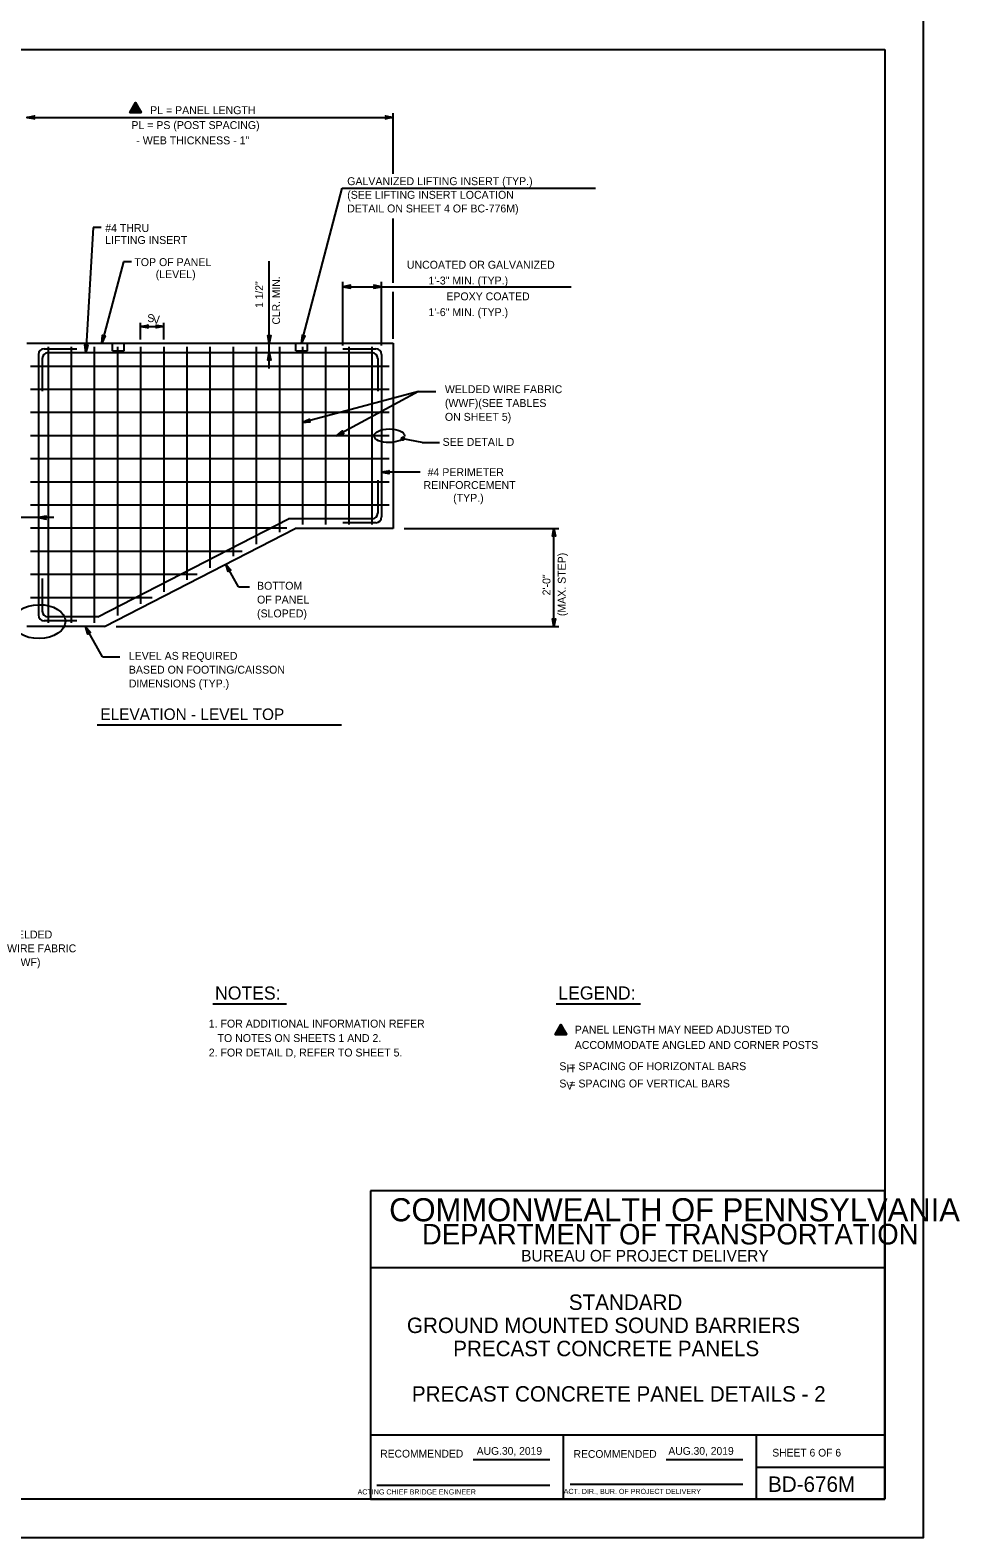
# Model space of a CAD drawing. Extents: x 3761 to 5458, y -616 to 1166.
# Drawn here: x 5096 to 5458, y -616 to -30 of the extents above; entities that cross this region are included whole.
import ezdxf

# ---------------------------------------------------------------- set-up
doc = ezdxf.new("R2010")
doc.units = 0
for name, color, linetype in [('1', 7, 'Continuous'), ('2', 7, 'Continuous'), ('PLT-BNDY', 7, 'Continuous')]:
    doc.layers.add(name, color=color, linetype=linetype)

msp = doc.modelspace()

# ---------------------------------------------------------------- linework, layer by layer
at = {"layer": '1'}
for p, q in [((5094.63, -63.74), (5237.13, -63.74)), ((5136.92, -60.5), (5136.92, -60.5)), ((5237.13, -85.73), (5237.13, -62.05)), ((5201.51, -151.51), (5217.37, -91.28)), ((5217.37, -91.28), (5315.89, -91.28)), ((5237.13, -128.07), (5237.13, -103.03)), ((5120.49, -106.64), (5117.63, -155.26)), ((5123.62, -106.64), (5120.49, -106.64)), ((5132.24, -119.99), (5123.81, -151.51)), ((5135.38, -119.99), (5132.24, -119.99)), ((5188.97, -161.48), (5188.97, -119.73)), ((5217.63, -152.49), (5217.63, -127.67)), ((5232.63, -152.49), (5232.63, -127.67)), ((5217.63, -129.63), (5306.42, -129.63)), ((5237.13, -149.92), (5237.13, -131.62)), ((5138.88, -150.2), (5138.88, -143.62)), ((5138.88, -145.08), (5147.88, -145.08)), ((5147.88, -150.2), (5147.88, -143.62)), ((5094.63, -151.51), (5237.13, -151.51)), ((5128.01, -154.51), (5128.01, -151.51)), ((5132.51, -154.51), (5132.51, -151.51)), ((5199.26, -154.51), (5199.26, -151.51)), ((5203.76, -154.51), (5203.76, -151.51)), ((5237.13, -151.51), (5237.13, -223.67)), ((5099.13, -156.01), (5099.13, -257.34)), ((5100.63, -157.51), (5100.63, -170.26)), ((5101.38, -153.76), (5114.13, -153.76)), ((5102.88, -153.01), (5102.88, -260.34)), ((5102.88, -155.26), (5228.88, -155.26)), ((5111.88, -153.01), (5111.88, -260.34)), ((5120.88, -153.01), (5120.88, -260.34)), ((5128.01, -154.51), (5132.51, -154.51)), ((5129.88, -153.01), (5129.88, -257.55)), ((5138.88, -153.01), (5138.88, -252.92)), ((5147.88, -153.01), (5147.88, -248.28)), ((5156.88, -153.01), (5156.88, -243.65)), ((5165.88, -153.01), (5165.88, -239.01)), ((5174.88, -153.01), (5174.88, -234.38)), ((5183.88, -153.01), (5183.88, -229.74)), ((5192.88, -153.01), (5192.88, -225.11)), ((5199.26, -154.51), (5203.76, -154.51)), ((5201.88, -153.01), (5201.88, -222.17)), ((5210.88, -153.01), (5210.88, -222.17)), ((5217.63, -153.76), (5230.38, -153.76)), ((5219.88, -153.01), (5219.88, -222.17)), ((5228.88, -153.01), (5228.88, -222.17)), ((5231.13, -157.51), (5231.13, -170.26)), ((5232.63, -156.01), (5232.63, -219.17)), ((5235.63, -160.59), (5096.13, -160.59)), ((5235.63, -169.59), (5096.13, -169.59)), ((5246.95, -170.37), (5201.88, -182.42)), ((5246.95, -170.37), (5215.05, -187.59)), ((5246.95, -170.37), (5253.68, -170.37)), ((5235.63, -178.59), (5096.13, -178.59)), ((5235.63, -187.59), (5096.13, -187.59)), ((5248.4, -190.25), (5240.91, -188.73)), ((5248.4, -190.25), (5255.14, -190.25)), ((5235.63, -196.59), (5096.13, -196.59)), ((5231.13, -204.92), (5231.13, -217.67)), ((5247.69, -201.75), (5232.63, -201.75)), ((5235.63, -205.59), (5096.13, -205.59)), ((5235.63, -214.59), (5096.13, -214.59)), ((5105.15, -219.44), (5057.23, -219.44)), ((5122.29, -258.09), (5196.41, -219.92)), ((5228.88, -219.92), (5196.41, -219.92)), ((5230.38, -221.42), (5217.63, -221.42)), ((5195.83, -223.59), (5096.13, -223.59)), ((5124.84, -261.84), (5198.96, -223.67)), ((5237.13, -223.67), (5198.96, -223.67)), ((5241.37, -223.67), (5301.6, -223.67)), ((5299.67, -261.84), (5299.67, -223.67)), ((5178.36, -232.59), (5096.13, -232.59)), ((5176.95, -246.34), (5172.01, -237.54)), ((5160.88, -241.59), (5096.13, -241.59)), ((5100.63, -243.09), (5100.63, -255.84)), ((5143.41, -250.59), (5096.13, -250.59)), ((5176.95, -246.34), (5181.32, -246.34)), ((5124.84, -261.84), (5094.63, -261.84)), ((5114.13, -259.59), (5101.38, -259.59)), ((5122.29, -258.09), (5102.88, -258.09)), ((5124.06, -273.62), (5117.45, -261.84)), ((5129.4, -261.84), (5301.6, -261.84)), ((5124.06, -273.62), (5130.8, -273.62)), ((5122.03, -300), (5217.08, -300)), ((5167.02, -408.54), (5195.59, -408.54)), ((5300.59, -408.54), (5333.38, -408.54)), ((5302.38, -419.19), (5302.38, -419.19))]:
    msp.add_line(p, q, dxfattribs=at)
for points in [[(5134.69, -61.79), (5139.15, -61.79), (5136.92, -57.92), (5134.69, -61.79)], [(5134.69, -61.79), (5136.92, -57.92), (5139.15, -61.79), (5134.69, -61.79), (5136.91, -58.03), (5139.08, -61.73), (5134.78, -61.74), (5136.92, -58.15), (5138.99, -61.68), (5134.88, -61.69), (5136.93, -58.26), (5138.89, -61.61), (5134.98, -61.64), (5136.92, -58.38), (5138.79, -61.56), (5135.09, -61.57), (5136.93, -58.51), (5138.68, -61.5), (5135.21, -61.5), (5136.92, -58.65), (5138.58, -61.44), (5135.31, -61.44), (5136.92, -58.79), (5138.47, -61.37), (5135.42, -61.38), (5136.92, -58.92), (5138.35, -61.3), (5135.52, -61.32), (5136.93, -59.04), (5138.21, -61.24), (5135.64, -61.25), (5136.93, -59.17), (5138.08, -61.15), (5135.76, -61.19), (5136.93, -59.32), (5137.96, -61.07), (5135.87, -61.13), (5136.93, -59.45), (5137.84, -61), (5136.01, -61.06), (5136.93, -59.58), (5137.73, -60.94), (5136.14, -61), (5136.93, -59.73), (5137.6, -60.87), (5136.28, -60.93), (5136.93, -59.86), (5137.47, -60.8), (5136.38, -60.86), (5136.92, -59.99), (5137.34, -60.73), (5136.51, -60.8), (5136.92, -60.11), (5137.24, -60.68), (5136.61, -60.74), (5136.92, -60.24), (5137.14, -60.62), (5136.72, -60.69), (5136.93, -60.36), (5137.05, -60.58), (5136.83, -60.61), (5136.92, -60.5), (5139.14, -61.77), (5136.92, -60.5), (5136.92, -57.95), (5136.93, -60.51), (5134.7, -61.78)], [(5094.63, -63.74), (5097.61, -63.18), (5097.38, -63.34), (5097.26, -63.54), (5097.23, -63.74), (5097.26, -63.94), (5097.38, -64.14), (5097.61, -64.3), (5094.63, -63.74), (5097.38, -64.14), (5097.26, -63.94), (5094.63, -63.74), (5097.23, -63.74), (5097.26, -63.54), (5094.63, -63.74), (5097.38, -63.34)], [(5237.13, -63.74), (5234.15, -64.3), (5234.38, -64.14), (5234.5, -63.94), (5234.53, -63.74), (5234.5, -63.54), (5234.38, -63.34), (5234.15, -63.18), (5237.13, -63.74), (5234.38, -63.34), (5234.5, -63.54), (5237.13, -63.74), (5234.53, -63.74), (5234.5, -63.94), (5237.13, -63.74), (5234.38, -64.14)], [(5217.63, -129.63), (5220.61, -130.18), (5220.5, -130.11), (5220.38, -130.03), (5220.33, -129.93), (5220.27, -129.83), (5220.25, -129.73), (5220.23, -129.63), (5220.25, -129.53), (5220.27, -129.43), (5220.33, -129.33), (5220.38, -129.23), (5220.5, -129.15), (5220.61, -129.07), (5217.63, -129.63), (5220.5, -129.15), (5220.38, -129.23), (5217.63, -129.63), (5220.33, -129.33), (5220.27, -129.43), (5217.63, -129.63), (5220.25, -129.53), (5220.23, -129.63), (5217.63, -129.63), (5220.25, -129.73), (5220.27, -129.83), (5217.63, -129.63), (5220.33, -129.93), (5220.38, -130.03), (5217.63, -129.63), (5220.5, -130.11)], [(5232.63, -129.63), (5229.65, -129.07), (5229.76, -129.15), (5229.88, -129.23), (5229.94, -129.33), (5230, -129.43), (5230.01, -129.53), (5230.03, -129.63), (5230.01, -129.73), (5230, -129.83), (5229.94, -129.93), (5229.88, -130.03), (5229.76, -130.11), (5229.65, -130.18), (5232.63, -129.63), (5229.76, -130.11), (5229.88, -130.03), (5232.63, -129.63), (5229.94, -129.93), (5230, -129.83), (5232.63, -129.63), (5230.01, -129.73), (5230.03, -129.63), (5232.63, -129.63), (5230.01, -129.53), (5230, -129.43), (5232.63, -129.63), (5229.94, -129.33), (5229.88, -129.23), (5232.63, -129.63), (5229.76, -129.15)], [(5138.88, -145.08), (5141.86, -144.52), (5141.63, -144.68), (5141.51, -144.88), (5141.48, -145.08), (5141.51, -145.28), (5141.63, -145.48), (5141.86, -145.64), (5138.88, -145.08), (5141.63, -145.48), (5141.51, -145.28), (5138.88, -145.08), (5141.48, -145.08), (5141.51, -144.88), (5138.88, -145.08), (5141.63, -144.68)], [(5147.88, -145.08), (5144.9, -145.64), (5145.13, -145.48), (5145.25, -145.28), (5145.28, -145.08), (5145.25, -144.88), (5145.13, -144.68), (5144.9, -144.52), (5147.88, -145.08), (5145.13, -144.68), (5145.25, -144.88), (5147.88, -145.08), (5145.28, -145.08), (5145.25, -145.28), (5147.88, -145.08), (5145.13, -145.48)], [(5117.63, -155.26), (5117.24, -152.25), (5117.39, -152.49), (5117.58, -152.62), (5117.78, -152.67), (5117.98, -152.64), (5118.19, -152.54), (5118.36, -152.32), (5117.63, -155.26), (5118.19, -152.54), (5117.98, -152.64), (5117.63, -155.26), (5117.78, -152.67), (5117.58, -152.62), (5117.63, -155.26), (5117.39, -152.49)], [(5123.81, -151.51), (5124.04, -148.49), (5124.09, -148.62), (5124.14, -148.75), (5124.22, -148.83), (5124.3, -148.92), (5124.39, -148.96), (5124.48, -149), (5124.58, -149.01), (5124.68, -149.02), (5124.8, -148.99), (5124.91, -148.96), (5125.01, -148.87), (5125.12, -148.77), (5123.81, -151.51), (5125.01, -148.87), (5124.91, -148.96), (5123.81, -151.51), (5124.8, -148.99), (5124.68, -149.02), (5123.81, -151.51), (5124.58, -149.01), (5124.48, -149), (5123.81, -151.51), (5124.39, -148.96), (5124.3, -148.92), (5123.81, -151.51), (5124.22, -148.83), (5124.14, -148.75), (5123.81, -151.51), (5124.09, -148.62)], [(5188.97, -151.51), (5188.41, -148.53), (5188.57, -148.76), (5188.77, -148.88), (5188.97, -148.91), (5189.17, -148.88), (5189.37, -148.76), (5189.53, -148.53), (5188.97, -151.51), (5189.37, -148.76), (5189.17, -148.88), (5188.97, -151.51), (5188.97, -148.91), (5188.77, -148.88), (5188.97, -151.51), (5188.57, -148.76)], [(5201.51, -151.51), (5202.87, -148.8), (5202.77, -148.89), (5202.66, -148.98), (5202.54, -149.01), (5202.43, -149.04), (5202.33, -149.03), (5202.23, -149.01), (5202.14, -148.97), (5202.05, -148.93), (5201.97, -148.84), (5201.89, -148.76), (5201.84, -148.62), (5201.8, -148.49), (5201.51, -151.51), (5201.84, -148.62), (5201.89, -148.76), (5201.51, -151.51), (5201.97, -148.84), (5202.05, -148.93), (5201.51, -151.51), (5202.14, -148.97), (5202.23, -149.01), (5201.51, -151.51), (5202.33, -149.03), (5202.43, -149.04), (5201.51, -151.51), (5202.54, -149.01), (5202.66, -148.98), (5201.51, -151.51), (5202.77, -148.89)], [(5188.97, -155.26), (5189.53, -158.24), (5189.37, -158.01), (5189.17, -157.9), (5188.97, -157.86), (5188.77, -157.9), (5188.57, -158.01), (5188.41, -158.24), (5188.97, -155.26), (5188.57, -158.01), (5188.77, -157.9), (5188.97, -155.26), (5188.97, -157.86), (5189.17, -157.9), (5188.97, -155.26), (5189.37, -158.01)], [(5201.88, -182.42), (5204.62, -181.11), (5204.53, -181.22), (5204.44, -181.33), (5204.4, -181.44), (5204.37, -181.55), (5204.38, -181.65), (5204.39, -181.75), (5204.43, -181.84), (5204.48, -181.94), (5204.56, -182.02), (5204.64, -182.1), (5204.77, -182.15), (5204.91, -182.19), (5201.88, -182.42), (5204.77, -182.15), (5204.64, -182.1), (5201.88, -182.42), (5204.56, -182.02), (5204.48, -181.94), (5201.88, -182.42), (5204.43, -181.84), (5204.39, -181.75), (5201.88, -182.42), (5204.38, -181.65), (5204.37, -181.55), (5201.88, -182.42), (5204.4, -181.44), (5204.44, -181.33), (5201.88, -182.42), (5204.53, -181.22)], [(5215.05, -187.59), (5217.41, -185.68), (5217.35, -185.8), (5217.28, -185.93), (5217.28, -186.05), (5217.27, -186.16), (5217.31, -186.26), (5217.34, -186.35), (5217.4, -186.43), (5217.46, -186.51), (5217.56, -186.57), (5217.66, -186.63), (5217.8, -186.65), (5217.94, -186.66), (5215.05, -187.59), (5217.8, -186.65), (5217.66, -186.63), (5215.05, -187.59), (5217.56, -186.57), (5217.46, -186.51), (5215.05, -187.59), (5217.4, -186.43), (5217.34, -186.35), (5215.05, -187.59), (5217.31, -186.26), (5217.27, -186.16), (5215.05, -187.59), (5217.28, -186.05), (5217.28, -185.93), (5215.05, -187.59), (5217.35, -185.8)], [(5232.63, -201.75), (5235.61, -201.19), (5235.5, -201.27), (5235.38, -201.35), (5235.32, -201.45), (5235.27, -201.55), (5235.25, -201.65), (5235.23, -201.75), (5235.25, -201.85), (5235.27, -201.95), (5235.32, -202.05), (5235.38, -202.15), (5235.5, -202.23), (5235.61, -202.31), (5232.63, -201.75), (5235.5, -202.23), (5235.38, -202.15), (5232.63, -201.75), (5235.32, -202.05), (5235.27, -201.95), (5232.63, -201.75), (5235.25, -201.85), (5235.23, -201.75), (5232.63, -201.75), (5235.25, -201.65), (5235.27, -201.55), (5232.63, -201.75), (5235.32, -201.45), (5235.38, -201.35), (5232.63, -201.75), (5235.5, -201.27)], [(5099.13, -219.44), (5102.11, -220), (5102, -219.92), (5101.88, -219.84), (5101.82, -219.74), (5101.77, -219.64), (5101.75, -219.54), (5101.73, -219.44), (5101.75, -219.34), (5101.77, -219.24), (5101.82, -219.14), (5101.88, -219.04), (5102, -218.96), (5102.11, -218.88), (5099.13, -219.44), (5102, -218.96), (5101.88, -219.04), (5099.13, -219.44), (5101.82, -219.14), (5101.77, -219.24), (5099.13, -219.44), (5101.75, -219.34), (5101.73, -219.44), (5099.13, -219.44), (5101.75, -219.54), (5101.77, -219.64), (5099.13, -219.44), (5101.82, -219.74), (5101.88, -219.84), (5099.13, -219.44), (5102, -219.92)], [(5299.67, -223.67), (5300.23, -226.65), (5300.07, -226.42), (5299.87, -226.3), (5299.67, -226.27), (5299.47, -226.3), (5299.27, -226.42), (5299.11, -226.65), (5299.67, -223.67), (5299.27, -226.42), (5299.47, -226.3), (5299.67, -223.67), (5299.67, -226.27), (5299.87, -226.3), (5299.67, -223.67), (5300.07, -226.42)], [(5172.01, -237.54), (5173.96, -239.87), (5173.71, -239.75), (5173.48, -239.74), (5173.29, -239.81), (5173.13, -239.94), (5173.01, -240.14), (5172.99, -240.42), (5172.01, -237.54), (5173.01, -240.14), (5173.13, -239.94), (5172.01, -237.54), (5173.29, -239.81), (5173.48, -239.74), (5172.01, -237.54), (5173.71, -239.75)], [(5117.45, -261.84), (5119.4, -264.17), (5119.15, -264.04), (5118.92, -264.04), (5118.72, -264.11), (5118.57, -264.23), (5118.45, -264.44), (5118.42, -264.71), (5117.45, -261.84), (5118.45, -264.44), (5118.57, -264.23), (5117.45, -261.84), (5118.72, -264.11), (5118.92, -264.04), (5117.45, -261.84), (5119.15, -264.04)], [(5299.67, -261.84), (5299.11, -258.86), (5299.27, -259.09), (5299.47, -259.2), (5299.67, -259.24), (5299.87, -259.2), (5300.07, -259.09), (5300.23, -258.86), (5299.67, -261.84), (5300.07, -259.09), (5299.87, -259.2), (5299.67, -261.84), (5299.67, -259.24), (5299.47, -259.2), (5299.67, -261.84), (5299.27, -259.09)], [(5300.15, -420.48), (5304.62, -420.48), (5302.38, -416.62), (5300.15, -420.48)], [(5300.15, -420.48), (5302.38, -416.62), (5304.62, -420.48), (5300.15, -420.48), (5302.38, -416.73), (5304.54, -420.43), (5300.24, -420.44), (5302.39, -416.84), (5304.45, -420.37), (5300.35, -420.39), (5302.39, -416.96), (5304.35, -420.3), (5300.44, -420.33), (5302.39, -417.08), (5304.26, -420.25), (5300.55, -420.26), (5302.39, -417.21), (5304.15, -420.2), (5300.67, -420.2), (5302.39, -417.35), (5304.04, -420.13), (5300.77, -420.14), (5302.38, -417.48), (5303.93, -420.06), (5300.88, -420.07), (5302.38, -417.61), (5303.81, -419.99), (5300.99, -420.01), (5302.4, -417.74), (5303.68, -419.93), (5301.1, -419.95), (5302.4, -417.87), (5303.54, -419.85), (5301.22, -419.89), (5302.4, -418.01), (5303.43, -419.77), (5301.34, -419.82), (5302.39, -418.15), (5303.31, -419.7), (5301.47, -419.75), (5302.4, -418.28), (5303.2, -419.64), (5301.6, -419.69), (5302.39, -418.42), (5303.07, -419.57), (5301.74, -419.62), (5302.39, -418.55), (5302.93, -419.49), (5301.85, -419.56), (5302.39, -418.68), (5302.81, -419.42), (5301.97, -419.5), (5302.39, -418.81), (5302.7, -419.38), (5302.08, -419.44), (5302.39, -418.93), (5302.61, -419.32), (5302.18, -419.38), (5302.39, -419.06), (5302.52, -419.27), (5302.3, -419.3), (5302.39, -419.2), (5304.6, -420.47), (5302.39, -419.2), (5302.39, -416.64), (5302.39, -419.21), (5300.16, -420.47)]]:
    msp.add_lwpolyline(points, dxfattribs=at)
for radius in [0.533, 0.267]:
    msp.add_circle((5240.91, -188.73), radius, dxfattribs=at)
for centre, start, end in [((5101.38, -156.01), 90, 180), ((5102.88, -157.51), 90, 180), ((5228.88, -157.51), 0, 90), ((5230.38, -156.01), 0, 90), ((5228.88, -217.67), 270, 360), ((5230.38, -219.17), 270, 0), ((5101.38, -257.34), 180, 270), ((5102.88, -255.84), 180, 270)]:
    msp.add_arc(centre, 2.25, start, end, dxfattribs=at)
for centre, major_axis, ratio in [((5235.63, -187.59), (-5.94, -0.09), 0.443512), ((5099.35, -259.88), (-10.3, -0.16), 0.638969)]:
    msp.add_ellipse(centre, major_axis=major_axis, ratio=ratio, dxfattribs=at)
at = {"layer": '2'}
for p, q in [((4642.34, -37.31), (5428.34, -37.31)), ((5428.34, -37.31), (5428.34, -601.31)), ((5428.34, -481.31), (5228.34, -481.31)), ((5228.34, -481.31), (5228.34, -601.31)), ((5428.34, -601.31), (5428.34, -481.31)), ((5428.34, -511.31), (5228.34, -511.31)), ((5428.34, -576.31), (5228.34, -576.31)), ((5303.34, -601.31), (5303.34, -576.31)), ((5378.34, -576.31), (5378.34, -601.31)), ((5268.31, -585.81), (5298.07, -585.81)), ((5343.31, -585.81), (5373.21, -585.81)), ((5378.34, -588.81), (5428.34, -588.81)), ((5230.84, -595.81), (5298.07, -595.81)), ((5305.97, -595.43), (5373.21, -595.43)), ((5428.34, -601.31), (4642.34, -601.31)), ((5228.34, -601.31), (5428.34, -601.31))]:
    msp.add_line(p, q, dxfattribs=at)
at = {"layer": 'PLT-BNDY'}
msp.add_lwpolyline([(4602.34, -22.31), (5443.34, -22.31), (5443.34, -616.31), (4602.34, -616.31)], close=True, dxfattribs=at)

# ---------------------------------------------------------------- texts
at = {"layer": '1'}
for s, height, p in [('PL = PANEL LENGTH', 3.072, (5142.61, -62.48)), ('PL = PS (POST SPACING)', 3.072, (5135.31, -68.28)), ('- WEB THICKNESS - 1"', 3.072, (5137.24, -74.23)), ('GALVANIZED LIFTING INSERT (TYP.)', 3.072, (5219.27, -90.1)), ('(SEE LIFTING INSERT LOCATION', 3.072, (5219.27, -95.41)), ('DETAIL ON SHEET 4 OF BC-776M)', 3.072, (5219.27, -100.72)), ('#4 THRU ', 3.072, (5125.13, -108.31)), ('LIFTING INSERT', 3.0721, (5125.13, -112.98)), ('TOP OF PANEL', 3.072, (5136.48, -121.59)), ('(LEVEL)', 3.072, (5144.78, -126.26)), ('UNCOATED OR GALVANIZED', 3.072, (5242.47, -122.61)), ('1\'-3" MIN. (TYP.)', 3.072, (5250.86, -128.75)), ('EPOXY COATED', 3.072, (5257.83, -134.9)), ('S', 3.07, (5141.5, -143.38)), ('1\'-6" MIN. (TYP.)', 3.072, (5250.86, -141.04)), ('V', 3.07, (5143.68, -144)), ('WELDED WIRE FABRIC', 3.072, (5257.27, -171.02)), ('(WWF)(SEE TABLES', 3.072, (5257.27, -176.39)), ('ON SHEET 5)', 3.072, (5257.27, -181.77)), ('SEE DETAIL D', 3.072, (5256.39, -191.51)), ('REINFORCEMENT', 3.072, (5248.96, -208.3)), ('#4 PERIMETER', 3.072, (5250.55, -203.3)), ('(TYP.) ', 3.072, (5260.48, -213.29)), ('BOTTOM', 3.072, (5184.2, -247.48)), ('OF PANEL', 3.072, (5184.2, -252.86)), ('(SLOPED)', 3.072, (5184.2, -258.24)), ('LEVEL AS REQUIRED', 3.072, (5134.33, -274.75)), ('BASED ON FOOTING/CAISSON', 3.072, (5134.33, -280.13)), ('DIMENSIONS (TYP.)', 3.072, (5134.33, -285.51)), ('ELEVATION - LEVEL TOP', 4.4774, (5123.24, -298.16)), ('WELDED', 3.072, (5086.96, -383.14)), ('WIRE FABRIC', 3.072, (5086.96, -388.52)), ('(WWF)', 3.072, (5086.96, -393.89)), ('NOTES:', 5.117, (5167.86, -406.91)), ('LEGEND:', 5.117, (5301.38, -406.91)), ('1. FOR ADDITIONAL INFORMATION REFER', 3.072, (5165.41, -417.8)), ('   TO NOTES ON SHEETS 1 AND 2.', 3.072, (5165.41, -423.43)), ('PANEL LENGTH MAY NEED ADJUSTED TO', 3.072, (5307.78, -420.16)), ('2. FOR DETAIL D, REFER TO SHEET 5.', 3.072, (5165.41, -429.06)), ('ACCOMMODATE ANGLED AND CORNER POSTS', 3.072, (5307.78, -426.11)), ('S = SPACING OF HORIZONTAL BARS', 3.072, (5301.78, -434.37)), ('H', 3.07, (5304.58, -435.2)), ('S = SPACING OF VERTICAL BARS', 3.072, (5301.78, -441.11)), ('V', 3.07, (5304.45, -441.93)), ('STANDARD', 6, (5305.48, -527.64)), ('GROUND MOUNTED SOUND BARRIERS', 6, (5242.5, -536.64)), ('PRECAST CONCRETE PANELS', 6, (5260.5, -545.64)), ('PRECAST CONCRETE PANEL DETAILS - 2', 6, (5244.42, -563.31)), ('SHEET 6 OF 6', 3, (5384.63, -584.68)), ('BD-676M', 6, (5382.97, -598.43))]:
    msp.add_text(s, height=height, dxfattribs=at).set_placement(p)
for s, height, p in [('1 1/2"', 3, (5186.53, -137.86)), ('CLR. MIN.', 3, (5193.13, -144.32)), ('(MAX. STEP)', 3.072, (5304.27, -257.76)), ('2\'-0"', 3.072, (5298.32, -249.68))]:
    msp.add_text(s, height=height, rotation=90, dxfattribs=at).set_placement(p)
at = {"layer": '2'}
for s, height, p in [('COMMONWEALTH OF PENNSYLVANIA', 9, (5235.59, -493.18)), ('DEPARTMENT OF TRANSPORTATION', 8.0002, (5248.34, -502.18)), ('BUREAU OF PROJECT DELIVERY', 4.5, (5286.93, -508.81)), ('AUG.30, 2019', 3, (5269.64, -584)), ('AUG.30, 2019', 3, (5344.19, -584)), ('       ACTING CHIEF BRIDGE ENGINEER', 2.0002, (5217.93, -599.43)), ('  ACT. DIR., BUR. OF PROJECT DELIVERY', 2.0002, (5301.93, -599.25))]:
    msp.add_text(s, height=height, dxfattribs=at).set_placement(p)
for p in [(5232.11, -585.06), (5307.33, -585.18)]:
    msp.add_text('RECOMMENDED', height=3, rotation=360, dxfattribs=at).set_placement(p)

doc.saveas('drawing.dxf')
